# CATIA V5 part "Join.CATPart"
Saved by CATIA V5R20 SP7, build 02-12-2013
Part number: Join
Bounding box of the stored display mesh (mm): x 5820.528 to 5831.958, y 30.246 to 40.406, z 798.045 to 810.999
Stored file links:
  C:\Users\CAS-\Desktop\Exercise Files\Join.CATPart
  D:\Birk\UTP_Covers\WIP\STANDOFF.CATPart
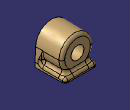
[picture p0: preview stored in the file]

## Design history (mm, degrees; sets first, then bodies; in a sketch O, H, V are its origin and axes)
Set1 "Join"
  DatumSurface1 to DatumSurface47
Body1 (main body)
